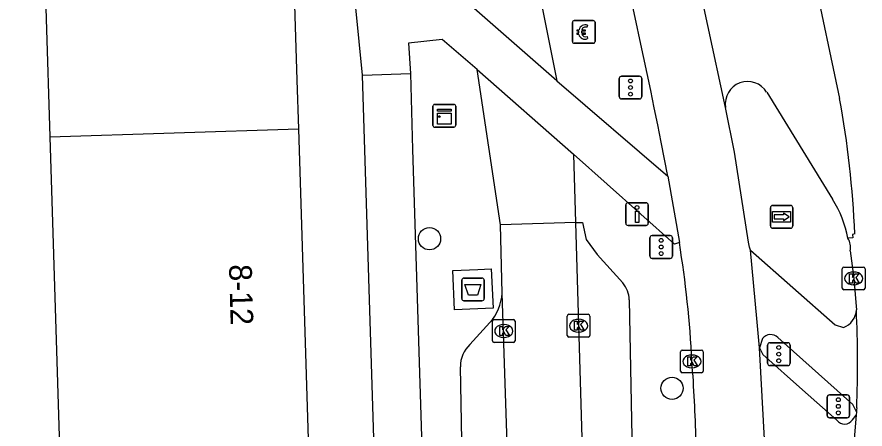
# Model space of a CAD drawing. Extents: x 161402 to 161933, y 381650 to 382313.
# Drawn here: x 161894.83 to 161932.17, y 382129.18 to 382147.3 of the extents above; entities that cross this region are included whole.
import ezdxf

# ---------------------------------------------------------------- set-up
doc = ezdxf.new("R2010")
doc.units = 0
for name, color, linetype in [('IMGEO_Afval_apart_plaats', 7, 'Continuous'), ('IMGEO_Betaalautomaat', 7, 'Continuous'), ('IMGEO_Boom', 7, 'Continuous'), ('IMGEO_Drukknoppaal', 7, 'Continuous'), ('IMGEO_Fietspad_gesloten', 7, 'Continuous'), ('IMGEO_Fietspad_open', 7, 'Continuous'), ('IMGEO_Kast', 7, 'Continuous'), ('IMGEO_Kolk', 7, 'Continuous'), ('IMGEO_OVBaan_gesloten', 7, 'Continuous'), ('IMGEO_Pand', 7, 'Continuous'), ('IMGEO_Pand_nummerreeks', 7, 'Continuous'), ('IMGEO_Parkeervlak_open', 7, 'Continuous'), ('IMGEO_Rijbaan_lokaal_gesloten', 7, 'Continuous'), ('IMGEO_Rijbaan_lokaal_open', 7, 'Continuous'), ('IMGEO_Verkeersregelinstallatiepaal', 7, 'Continuous'), ('IMGEO_Voetpad_gesloten', 7, 'Continuous'), ('IMGEO_Voetpad_open', 7, 'Continuous'), ('IMGEO_Wegwijzer', 7, 'Continuous')]:
    doc.layers.add(name, color=color, linetype=linetype)

msp = doc.modelspace()

# ---------------------------------------------------------------- linework, layer by layer
at = {"layer": 'IMGEO_Afval_apart_plaats'}
for p, q in [((161914.415, 382134.919), (161914.415, 382135.719)), ((161914.415, 382135.719), (161914.415, 382134.919)), ((161914.515, 382135.819), (161915.305, 382135.819)), ((161915.305, 382135.819), (161914.515, 382135.819)), ((161915.405, 382135.719), (161915.405, 382134.919)), ((161915.405, 382134.919), (161915.405, 382135.719)), ((161915.305, 382134.819), (161914.515, 382134.819)), ((161914.515, 382134.819), (161915.305, 382134.819))]:
    msp.add_line(p, q, dxfattribs=at)
msp.add_lwpolyline([(161914.558, 382135.533), (161915.262, 382135.533), (161915.113, 382135.063), (161914.707, 382135.063), (161914.558, 382135.533)], dxfattribs=at)
for centre, start, end in [((161914.515, 382135.719), 90, 180), ((161914.515, 382135.719), 90, 180), ((161915.305, 382135.719), 0, 90), ((161915.305, 382135.719), 360, 90), ((161914.515, 382134.919), 180, 270), ((161914.515, 382134.919), 180, 270), ((161915.305, 382134.919), 270, 0), ((161915.305, 382134.919), 270, 0)]:
    msp.add_arc(centre, 0.1, start, end, dxfattribs=at)
at = {"layer": 'IMGEO_Betaalautomaat'}
for p, q in [((161919.36, 382147.139), (161920.201, 382147.139)), ((161920.201, 382147.139), (161919.36, 382147.139)), ((161919.285, 382146.215), (161919.285, 382147.056)), ((161919.285, 382147.056), (161919.285, 382146.215)), ((161919.947, 382146.944), (161919.93, 382146.844)), ((161920.284, 382147.065), (161920.284, 382146.224)), ((161920.284, 382146.224), (161920.284, 382147.065)), ((161919.568, 382146.603), (161919.568, 382146.671)), ((161919.689, 382146.671), (161919.689, 382146.603)), ((161919.934, 382146.438), (161919.956, 382146.351)), ((161920.21, 382146.14), (161919.369, 382146.14)), ((161919.369, 382146.14), (161920.21, 382146.14))]:
    msp.add_line(p, q, dxfattribs=at)
for points in [[(161919.568, 382146.671), (161919.499, 382146.671), (161919.499, 382146.74), (161919.578, 382146.74)], [(161919.573, 382146.534), (161919.499, 382146.534), (161919.499, 382146.603), (161919.568, 382146.603)], [(161919.7, 382146.74), (161919.847, 382146.74), (161919.847, 382146.671), (161919.689, 382146.671)], [(161919.689, 382146.603), (161919.847, 382146.603), (161919.847, 382146.534), (161919.703, 382146.534)]]:
    msp.add_lwpolyline(points, dxfattribs=at)
for centre, radius, start, end in [((161919.363, 382147.062), 0.0779, 92.4484, 184.2845), ((161919.363, 382147.062), 0.0779, 92.4484, 184.2845), ((161920.207, 382147.062), 0.0779, 2.4484, 94.2845), ((161920.207, 382147.062), 0.0779, 2.4484, 94.2845), ((161919.861, 382146.664), 0.293, 73.014, 165.0139), ((161919.867, 382146.677), 0.179, 69.3236, 159.5683), ((161919.834, 382146.589), 0.267, 191.8096, 297.0389), ((161919.867, 382146.604), 0.179, 202.7625, 291.8693), ((161919.363, 382146.218), 0.0779, 182.4484, 274.2845), ((161919.363, 382146.218), 0.0779, 182.4484, 274.2845), ((161920.207, 382146.218), 0.0779, 272.4484, 4.2845), ((161920.207, 382146.218), 0.0779, 272.4484, 4.2845)]:
    msp.add_arc(centre, radius, start, end, dxfattribs=at)
at = {"layer": 'IMGEO_Boom'}
for centre in [(161912.997, 382137.546), (161923.675, 382130.973)]:
    msp.add_circle(centre, 0.489, dxfattribs=at)
at = {"layer": 'IMGEO_Drukknoppaal'}
for p, q in [((161921.639, 382138.231), (161921.639, 382139.031)), ((161921.639, 382139.031), (161921.639, 382138.231)), ((161921.739, 382139.131), (161922.529, 382139.131)), ((161922.529, 382139.131), (161921.739, 382139.131)), ((161922.629, 382139.031), (161922.629, 382138.231)), ((161922.629, 382138.231), (161922.629, 382139.031)), ((161922.529, 382138.131), (161921.739, 382138.131)), ((161921.739, 382138.131), (161922.529, 382138.131))]:
    msp.add_line(p, q, dxfattribs=at)
msp.add_lwpolyline([(161922.209, 382138.756), (161922.209, 382138.256), (161922.059, 382138.256), (161922.059, 382138.756), (161922.209, 382138.756)], dxfattribs=at)
msp.add_circle((161922.134, 382138.921), 0.085, dxfattribs=at)
for centre, start, end in [((161921.739, 382139.031), 90, 180), ((161921.739, 382139.031), 90, 180), ((161922.529, 382139.031), 0, 90), ((161922.529, 382139.031), 360, 90), ((161921.739, 382138.231), 180, 270), ((161921.739, 382138.231), 180, 270), ((161922.529, 382138.231), 270, 0), ((161922.529, 382138.231), 270, 0)]:
    msp.add_arc(centre, 0.1, start, end, dxfattribs=at)
at = {"layer": 'IMGEO_Fietspad_gesloten'}
for points in [[(161910.052, 382144.744), (161909.457, 382150.678)], [(161915.099, 382144.987), (161913.561, 382146.309), (161912.077, 382146.142), (161912.16, 382144.813)], [(161910.052, 382144.744), (161912.16, 382144.813)], [(161918.606, 382144.49), (161923.494, 382140.293)], [(161923.997, 382137.377), (161923.784, 382137.305), (161919.334, 382141.264)]]:
    msp.add_lwpolyline(points, dxfattribs=at)
at = {"layer": 'IMGEO_Fietspad_open'}
for points in [[(161911.019, 382075.595), (161911.485, 382092.573), (161911.516, 382094.566), (161911.423, 382100.579), (161910.052, 382144.744)], [(161912.16, 382144.813), (161912.252, 382141.473), (161913.518, 382100.778), (161913.546, 382089.832), (161913.149, 382075.567)], [(161927.126, 382137.05), (161930.858, 382133.769), (161931.223, 382133.648)], [(161927.65, 382133.156), (161927.527, 382132.744)], [(161931.796, 382129.943), (161931.63, 382130.26), (161928.335, 382133.198)]]:
    msp.add_lwpolyline(points, dxfattribs=at)
for centre, radius, start, end in [((161930.934, 382134.454), 0.856, 289.7495, 357.4717), ((161928.011, 382132.876), 0.457, 44.81, 142.2073)]:
    msp.add_arc(centre, radius, start, end, dxfattribs=at)
at = {"layer": 'IMGEO_Kast'}
for p, q in [((161913.224, 382143.454), (161914.065, 382143.454)), ((161914.065, 382143.454), (161913.224, 382143.454)), ((161913.149, 382142.529), (161913.149, 382143.37)), ((161913.149, 382143.37), (161913.149, 382142.529)), ((161914.149, 382143.379), (161914.149, 382142.538)), ((161914.149, 382142.538), (161914.149, 382143.379)), ((161914.074, 382142.454), (161913.233, 382142.454)), ((161913.233, 382142.454), (161914.074, 382142.454))]:
    msp.add_line(p, q, dxfattribs=at)
for points in [[(161913.344, 382143.244), (161913.944, 382143.244), (161913.944, 382143.159), (161913.344, 382143.159), (161913.344, 382143.244)], [(161913.344, 382143.069), (161913.944, 382143.069), (161913.944, 382142.58), (161913.344, 382142.58), (161913.344, 382143.069)]]:
    msp.add_lwpolyline(points, dxfattribs=at)
msp.add_circle((161913.428, 382142.918), 0.0377, dxfattribs=at)
for centre, start, end in [((161913.227, 382143.376), 92.4484, 184.2845), ((161913.227, 382143.376), 92.4484, 184.2845), ((161914.071, 382143.376), 2.4484, 94.2845), ((161914.071, 382143.376), 2.4484, 94.2845), ((161913.227, 382142.532), 182.4484, 274.2845), ((161913.227, 382142.532), 182.4484, 274.2845), ((161914.071, 382142.532), 272.4484, 4.2845), ((161914.071, 382142.532), 272.4484, 4.2845)]:
    msp.add_arc(centre, 0.0779, start, end, dxfattribs=at)
at = {"layer": 'IMGEO_Kolk'}
for p, q in [((161931.244, 382136.301), (161932.096, 382136.301)), ((161931.169, 382135.375), (161931.169, 382136.227)), ((161931.657, 382136.081), (161931.682, 382136.081)), ((161932.17, 382136.227), (161932.17, 382135.375)), ((161932.096, 382135.301), (161931.244, 382135.301)), ((161931.68, 382135.521), (161931.655, 382135.521)), ((161919.059, 382133.298), (161919.059, 382134.15)), ((161919.134, 382134.224), (161919.986, 382134.224)), ((161920.06, 382134.15), (161920.06, 382133.298)), ((161915.766, 382133.064), (161915.766, 382133.916)), ((161915.841, 382133.99), (161916.693, 382133.99)), ((161916.254, 382133.77), (161916.279, 382133.77)), ((161916.767, 382133.916), (161916.767, 382133.064)), ((161919.547, 382134.004), (161919.572, 382134.004)), ((161919.57, 382133.444), (161919.545, 382133.444)), ((161916.693, 382132.99), (161915.841, 382132.99)), ((161916.277, 382133.21), (161916.252, 382133.21)), ((161919.986, 382133.224), (161919.134, 382133.224)), ((161924.048, 382131.728), (161924.048, 382132.58)), ((161924.123, 382132.654), (161924.975, 382132.654)), ((161925.049, 382132.58), (161925.049, 382131.728)), ((161924.536, 382132.434), (161924.561, 382132.434)), ((161924.559, 382131.874), (161924.534, 382131.874)), ((161924.975, 382131.654), (161924.123, 382131.654))]:
    msp.add_line(p, q, dxfattribs=at)
for points in [[(161931.244, 382136.301), (161932.096, 382136.301)], [(161931.169, 382135.375), (161931.169, 382136.227)], [(161931.49, 382136.001), (161931.613, 382136.001), (161931.613, 382135.85), (161931.743, 382136.001), (161931.907, 382136.001), (161931.761, 382135.85), (161931.914, 382135.601), (161931.762, 382135.601), (161931.677, 382135.765), (161931.613, 382135.698), (161931.613, 382135.601), (161931.49, 382135.601), (161931.49, 382136.001)], [(161932.17, 382136.227), (161932.17, 382135.375)], [(161932.096, 382135.301), (161931.244, 382135.301)], [(161919.059, 382133.298), (161919.059, 382134.15)], [(161919.134, 382134.224), (161919.986, 382134.224)], [(161920.06, 382134.15), (161920.06, 382133.298)], [(161915.766, 382133.064), (161915.766, 382133.916)], [(161915.841, 382133.99), (161916.693, 382133.99)], [(161916.087, 382133.69), (161916.21, 382133.69), (161916.21, 382133.539), (161916.34, 382133.69), (161916.504, 382133.69), (161916.358, 382133.539), (161916.511, 382133.29), (161916.359, 382133.29), (161916.274, 382133.454), (161916.21, 382133.387), (161916.21, 382133.29), (161916.087, 382133.29), (161916.087, 382133.69)], [(161916.767, 382133.916), (161916.767, 382133.064)], [(161919.38, 382133.924), (161919.503, 382133.924), (161919.503, 382133.773), (161919.633, 382133.924), (161919.797, 382133.924), (161919.651, 382133.773), (161919.804, 382133.524), (161919.652, 382133.524), (161919.567, 382133.688), (161919.503, 382133.621), (161919.503, 382133.524), (161919.38, 382133.524), (161919.38, 382133.924)], [(161916.693, 382132.99), (161915.841, 382132.99)], [(161919.986, 382133.224), (161919.134, 382133.224)], [(161924.048, 382131.728), (161924.048, 382132.58)], [(161924.123, 382132.654), (161924.975, 382132.654)], [(161925.049, 382132.58), (161925.049, 382131.728)], [(161924.369, 382132.354), (161924.492, 382132.354), (161924.492, 382132.203), (161924.622, 382132.354), (161924.786, 382132.354), (161924.64, 382132.203), (161924.793, 382131.954), (161924.641, 382131.954), (161924.556, 382132.118), (161924.492, 382132.051), (161924.492, 382131.954), (161924.369, 382131.954), (161924.369, 382132.354)], [(161924.975, 382131.654), (161924.123, 382131.654)]]:
    msp.add_lwpolyline(points, dxfattribs=at)
for centre, start, end in [((161931.246, 382136.225), 91.552, 178.448), ((161931.246, 382136.225), 91.552, 178.448), ((161932.094, 382136.225), 1.552, 88.448), ((161932.094, 382136.225), 1.552, 88.448), ((161931.246, 382135.377), 181.552, 268.448), ((161931.246, 382135.377), 181.552, 268.448), ((161932.094, 382135.377), 271.552, 358.448), ((161932.094, 382135.377), 271.552, 358.448), ((161919.136, 382134.148), 91.552, 178.448), ((161919.136, 382134.148), 91.552, 178.448), ((161919.984, 382134.148), 1.552, 88.448), ((161919.984, 382134.148), 1.552, 88.448), ((161915.843, 382133.914), 91.552, 178.448), ((161915.843, 382133.914), 91.552, 178.448), ((161916.691, 382133.914), 1.552, 88.448), ((161916.691, 382133.914), 1.552, 88.448), ((161915.843, 382133.066), 181.552, 268.448), ((161915.843, 382133.066), 181.552, 268.448), ((161916.691, 382133.066), 271.552, 358.448), ((161916.691, 382133.066), 271.552, 358.448), ((161919.136, 382133.3), 181.552, 268.448), ((161919.136, 382133.3), 181.552, 268.448), ((161919.984, 382133.3), 271.552, 358.448), ((161919.984, 382133.3), 271.552, 358.448), ((161924.125, 382132.578), 91.552, 178.448), ((161924.125, 382132.578), 91.552, 178.448), ((161924.973, 382132.578), 1.552, 88.448), ((161924.973, 382132.578), 1.552, 88.448), ((161924.125, 382131.73), 181.552, 268.448), ((161924.125, 382131.73), 181.552, 268.448), ((161924.973, 382131.73), 271.552, 358.448), ((161924.973, 382131.73), 271.552, 358.448)]:
    msp.add_arc(centre, 0.0765, start, end, dxfattribs=at)
for centre, major_axis, ratio, start_param, end_param in [((161931.656, 382135.801), (-0.387, 0.002), 0.722429, 4.712389, 7.853982), ((161931.681, 382135.801), (-0.39, 0.002), 0.717154, 1.570796, 4.712389), ((161916.253, 382133.49), (-0.387, 0.002), 0.722429, 4.712389, 7.853982), ((161916.278, 382133.49), (-0.39, 0.002), 0.717154, 1.570796, 4.712389), ((161919.546, 382133.724), (-0.387, 0.002), 0.722429, 4.712389, 7.853982), ((161919.571, 382133.724), (-0.39, 0.002), 0.717154, 1.570796, 4.712389), ((161924.535, 382132.154), (-0.387, 0.002), 0.722429, 4.712389, 7.853982), ((161924.56, 382132.154), (-0.39, 0.002), 0.717154, 1.570796, 4.712389)]:
    msp.add_ellipse(centre, major_axis=major_axis, ratio=ratio, start_param=start_param, end_param=end_param, dxfattribs=at)
at = {"layer": 'IMGEO_OVBaan_gesloten'}
for points in [[(161929.259, 382151.489), (161929.41, 382151.511), (161929.894, 382149.203), (161931.045, 382143.716)], [(161931.716, 382137.757), (161931.613, 382137.739), (161931.634, 382137.591), (161931.418, 382137.566)], [(161931.522, 382137.019), (161931.672, 382135.801), (161931.78, 382134.588), (161931.789, 382134.416)], [(161931.803, 382130.106), (161931.799, 382130.025), (161931.796, 382129.943)], [(161931.782, 382129.797), (161931.462, 382125.963)], [(161931.796, 382129.943), (161931.782, 382129.797)]]:
    msp.add_lwpolyline(points, dxfattribs=at)
for centre, radius, start, end in [((161890.537, 382136.137), 41.211, 2.2523, 10.5969), ((161930.776, 382137.161), 0.76, 349.2636, 32.2665), ((161882.414, 382132.101), 49.429, 357.6873, 2.6849)]:
    msp.add_arc(centre, radius, start, end, dxfattribs=at)
at = {"layer": 'IMGEO_Pand'}
for points in [[(161906.731, 382158.368), (161906.736, 382158.205), (161907.16, 382144.524), (161907.227, 382142.376)], [(161895.524, 382158.015), (161895.537, 382157.595), (161895.793, 382157.603), (161896.284, 382142.031)], [(161896.284, 382142.031), (161907.227, 382142.376)], [(161907.227, 382142.376), (161907.722, 382126.383)], [(161896.284, 382142.031), (161896.788, 382126.039)]]:
    msp.add_lwpolyline(points, dxfattribs=at)
at = {"layer": 'IMGEO_Parkeervlak_open'}
for points in [[(161919.422, 382138.255), (161919.734, 382138.264), (161919.887, 382137.517), (161920.372, 382136.861), (161921.503, 382135.603)], [(161921.789, 382134.855), (161922.143, 382116.78), (161922.135, 382111.73)], [(161914.776, 382132.894), (161915.658, 382133.86)], [(161914.31, 382106.685), (161914.634, 382112.711), (161914.66, 382115.753), (161914.358, 382131.92)]]:
    msp.add_lwpolyline(points, dxfattribs=at)
for centre, radius, start, end in [((161920.665, 382134.854), 1.124, 0.0561, 41.7929), ((161914.158, 382135.232), 2.033, 317.561, 357.7234), ((161915.644, 382131.945), 1.286, 132.4439, 181.1021)]:
    msp.add_arc(centre, radius, start, end, dxfattribs=at)
at = {"layer": 'IMGEO_Rijbaan_lokaal_gesloten'}
for points in [[(161926.032, 382143.324), (161923.698, 382154.142), (161918.698, 382173.962), (161914.783, 382185.665), (161890.773, 382250.034), (161885.821, 382262.869), (161874.965, 382293.393)], [(161927.84, 382143.988), (161930.743, 382139.284)], [(161927.126, 382137.05), (161927.083, 382137.172), (161927.039, 382137.391), (161926.423, 382141.357), (161926.032, 382143.324)], [(161923.494, 382140.293), (161923.997, 382137.377)], [(161927.527, 382132.744), (161927.407, 382134.036), (161927.126, 382137.05)], [(161927.762, 382128.469), (161927.527, 382132.744)]]:
    msp.add_lwpolyline(points, dxfattribs=at)
for centre, radius, start, end in [((161592.988, 382075.551), 336.787, 11.08317, 15.26628), ((161926.999, 382143.484), 0.98, 30.948, 189.3842), ((161926.475, 382136.615), 5.034, 10.8851, 32.0145), ((161876.941, 382129.763), 47.668, 2.875, 9.191), ((161862.475, 382127.256), 62.267, 1.29538, 4.51131)]:
    msp.add_arc(centre, radius, start, end, dxfattribs=at)
at = {"layer": 'IMGEO_Rijbaan_lokaal_open'}
for points in [[(161917.321, 382150.865), (161918.606, 382144.49)], [(161918.606, 382144.49), (161914.606, 382147.976)], [(161916.121, 382138.162), (161915.099, 382144.987)], [(161915.099, 382144.987), (161919.334, 382141.264)], [(161919.334, 382141.264), (161919.422, 382138.255)], [(161919.422, 382138.255), (161916.121, 382138.162)], [(161919.422, 382138.255), (161919.989, 382118.8)], [(161916.189, 382135.151), (161916.121, 382138.162)], [(161916.779, 382117.545), (161916.189, 382135.151)]]:
    msp.add_lwpolyline(points, dxfattribs=at)
at = {"layer": 'IMGEO_Verkeersregelinstallatiepaal'}
for p, q in [((161921.352, 382143.795), (161921.352, 382144.595)), ((161921.352, 382144.595), (161921.352, 382143.795)), ((161921.452, 382144.695), (161922.242, 382144.695)), ((161922.242, 382144.695), (161921.452, 382144.695)), ((161922.342, 382144.595), (161922.342, 382143.795)), ((161922.342, 382143.795), (161922.342, 382144.595)), ((161922.242, 382143.695), (161921.452, 382143.695)), ((161921.452, 382143.695), (161922.242, 382143.695)), ((161922.701, 382136.785), (161922.701, 382137.585)), ((161922.701, 382137.585), (161922.701, 382136.785)), ((161922.801, 382137.685), (161923.591, 382137.685)), ((161923.591, 382137.685), (161922.801, 382137.685)), ((161923.691, 382137.585), (161923.691, 382136.785)), ((161923.691, 382136.785), (161923.691, 382137.585)), ((161923.591, 382136.685), (161922.801, 382136.685)), ((161922.801, 382136.685), (161923.591, 382136.685)), ((161927.977, 382132.973), (161928.767, 382132.973)), ((161928.767, 382132.973), (161927.977, 382132.973)), ((161927.877, 382132.073), (161927.877, 382132.873)), ((161927.877, 382132.873), (161927.877, 382132.073)), ((161928.867, 382132.873), (161928.867, 382132.073)), ((161928.867, 382132.073), (161928.867, 382132.873)), ((161928.767, 382131.973), (161927.977, 382131.973)), ((161927.977, 382131.973), (161928.767, 382131.973)), ((161930.5, 382129.779), (161930.5, 382130.579)), ((161930.5, 382130.579), (161930.5, 382129.779)), ((161930.6, 382130.679), (161931.39, 382130.679)), ((161931.39, 382130.679), (161930.6, 382130.679)), ((161931.49, 382130.579), (161931.49, 382129.779)), ((161931.49, 382129.779), (161931.49, 382130.579)), ((161931.39, 382129.679), (161930.6, 382129.679)), ((161930.6, 382129.679), (161931.39, 382129.679))]:
    msp.add_line(p, q, dxfattribs=at)
for centre in [(161921.847, 382144.485), (161921.847, 382144.195), (161921.847, 382143.905), (161923.196, 382137.475), (161923.196, 382137.185), (161923.196, 382136.895), (161928.372, 382132.763), (161928.372, 382132.473), (161928.372, 382132.183), (161930.995, 382130.469), (161930.995, 382130.179), (161930.995, 382129.889)]:
    msp.add_circle(centre, 0.085, dxfattribs=at)
for centre, start, end in [((161921.452, 382144.595), 90, 180), ((161921.452, 382144.595), 90, 180), ((161922.242, 382144.595), 0, 90), ((161922.242, 382144.595), 360, 90), ((161921.452, 382143.795), 180, 270), ((161921.452, 382143.795), 180, 270), ((161922.242, 382143.795), 270, 0), ((161922.242, 382143.795), 270, 0), ((161922.801, 382137.585), 90, 180), ((161922.801, 382137.585), 90, 180), ((161923.591, 382137.585), 0, 90), ((161923.591, 382137.585), 360, 90), ((161922.801, 382136.785), 180, 270), ((161922.801, 382136.785), 180, 270), ((161923.591, 382136.785), 270, 0), ((161923.591, 382136.785), 270, 0), ((161927.977, 382132.873), 90, 180), ((161927.977, 382132.873), 90, 180), ((161928.767, 382132.873), 0, 90), ((161928.767, 382132.873), 360, 90), ((161927.977, 382132.073), 180, 270), ((161927.977, 382132.073), 180, 270), ((161928.767, 382132.073), 270, 0), ((161928.767, 382132.073), 270, 0), ((161930.6, 382130.579), 90, 180), ((161930.6, 382130.579), 90, 180), ((161931.39, 382130.579), 0, 90), ((161931.39, 382130.579), 360, 90), ((161930.6, 382129.779), 180, 270), ((161930.6, 382129.779), 180, 270), ((161931.39, 382129.779), 270, 0), ((161931.39, 382129.779), 270, 0)]:
    msp.add_arc(centre, 0.1, start, end, dxfattribs=at)
at = {"layer": 'IMGEO_Voetpad_gesloten'}
msp.add_lwpolyline([(161915.119, 382136.202), (161915.711, 382136.231), (161915.796, 382134.498), (161914.102, 382134.415), (161914.017, 382136.148), (161915.119, 382136.202)], dxfattribs=at)
at = {"layer": 'IMGEO_Voetpad_open'}
for points in [[(161927.527, 382132.744), (161927.665, 382132.456), (161929.414, 382130.904), (161930.93, 382129.564)], [(161931.618, 382129.586), (161931.782, 382129.797)]]:
    msp.add_lwpolyline(points, dxfattribs=at)
msp.add_arc((161931.266, 382129.821), 0.423, 217.3738, 326.2892, dxfattribs=at)
at = {"layer": 'IMGEO_Wegwijzer'}
for p, q in [((161928.102, 382139.01), (161928.892, 382139.01)), ((161928.892, 382139.01), (161928.102, 382139.01)), ((161928.002, 382138.11), (161928.002, 382138.91)), ((161928.002, 382138.91), (161928.002, 382138.11)), ((161928.992, 382138.91), (161928.992, 382138.11)), ((161928.992, 382138.11), (161928.992, 382138.91)), ((161928.892, 382138.01), (161928.102, 382138.01)), ((161928.102, 382138.01), (161928.892, 382138.01))]:
    msp.add_line(p, q, dxfattribs=at)
for points in [[(161928.103, 382138.742), (161928.891, 382138.742), (161928.891, 382138.278), (161928.103, 382138.278), (161928.103, 382138.742)], [(161928.168, 382138.594), (161928.168, 382138.51), (161928.168, 382138.426), (161928.579, 382138.426), (161928.579, 382138.343), (161928.826, 382138.51), (161928.579, 382138.677), (161928.579, 382138.594), (161928.168, 382138.594)]]:
    msp.add_lwpolyline(points, dxfattribs=at)
for centre, start, end in [((161928.102, 382138.91), 90, 180), ((161928.102, 382138.91), 90, 180), ((161928.892, 382138.91), 0, 90), ((161928.892, 382138.91), 360, 90), ((161928.102, 382138.11), 180, 270), ((161928.102, 382138.11), 180, 270), ((161928.892, 382138.11), 270, 0), ((161928.892, 382138.11), 270, 0)]:
    msp.add_arc(centre, 0.1, start, end, dxfattribs=at)

# ---------------------------------------------------------------- texts
at = {"layer": 'IMGEO_Pand_nummerreeks'}
msp.add_text('8-12', height=1, rotation=271.6523, dxfattribs=at).set_placement((161904.168, 382136.411))

doc.saveas('drawing.dxf')
